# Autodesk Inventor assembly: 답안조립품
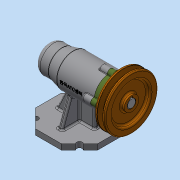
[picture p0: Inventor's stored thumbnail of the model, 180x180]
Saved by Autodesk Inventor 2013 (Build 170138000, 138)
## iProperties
Created: 2019-12
Part Number: 답안조립품
Document SubType Name: Assembly
Designer: Administrator
Author: Administrator
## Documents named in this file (12)
- C:\Users\Administrator\Desktop\491204V1033\답안조립품.iam
- C:\Users\Administrator\Desktop\491204V1033\본체.ipt
- C:\Users\Administrator\Desktop\491204V1033\베어링 6004.ipt
- C:\Users\Administrator\Desktop\491204V1033\축.ipt
- C:\Users\Administrator\Desktop\491204V1033\어댑터슬리브.ipt
- C:\Users\Administrator\Desktop\491204V1033\볼트 M4.ipt
- C:\Users\Administrator\Desktop\491204V1033\베어링 51202.ipt
- C:\Users\Administrator\Desktop\491204V1033\커버.ipt
- C:\Users\Administrator\Desktop\491204V1033\오일 실.ipt
- C:\Users\Administrator\Desktop\491204V1033\키 5 x 5 x 16.ipt
- C:\Users\Administrator\Desktop\491204V1033\V벨트풀리.ipt
- C:\Users\Administrator\Desktop\491204V1033\멈춤나사 M3.ipt
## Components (1 placed, 1 different names)
1. V벨트풀리:1
